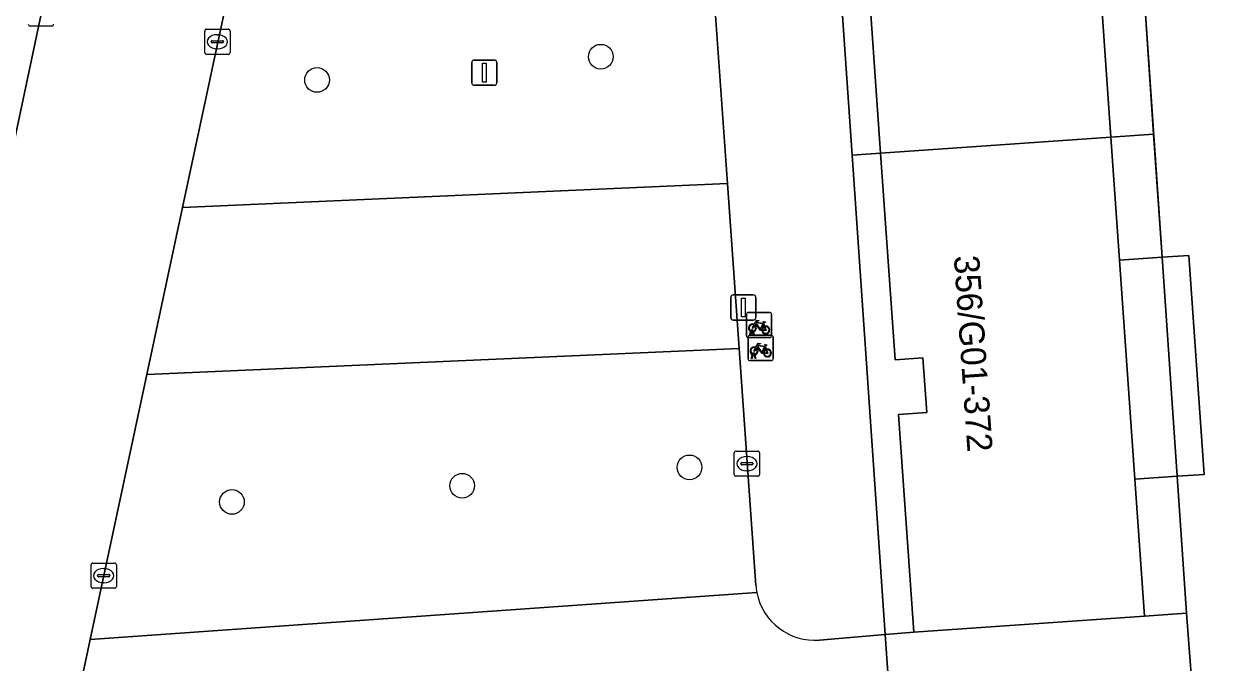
# Model space of a CAD drawing. Extents: x 161248 to 161848, y 384871 to 385383.
# Drawn here: x 161705.19 to 161753.01, y 385039.74 to 385065.04 of the extents above; entities that cross this region are included whole.
import ezdxf

# ---------------------------------------------------------------- set-up
doc = ezdxf.new("R2010")
doc.units = 0
for name, color, linetype in [('IMGEO_Boom', 7, 'Continuous'), ('IMGEO_Fietsenrek', 7, 'Continuous'), ('IMGEO_Kolk', 7, 'Continuous'), ('IMGEO_Lichtmast', 7, 'Continuous'), ('IMGEO_Pand', 7, 'Continuous'), ('IMGEO_Pand_nummerreeks', 7, 'Continuous'), ('IMGEO_Pand_overbouw', 7, 'Continuous'), ('IMGEO_Parkeervlak_open', 7, 'Continuous'), ('IMGEO_Rijbaan_lokaal_open', 7, 'Continuous'), ('IMGEO_Voetpad_open', 7, 'Continuous')]:
    doc.layers.add(name, color=color, linetype=linetype)

msp = doc.modelspace()

# ---------------------------------------------------------------- linework, layer by layer
at = {"layer": 'IMGEO_Boom'}
for centre in [(161728.021, 385063.749), (161716.786, 385062.828), (161731.533, 385047.481), (161722.532, 385046.752), (161713.416, 385046.112)]:
    msp.add_circle(centre, 0.489, dxfattribs=at)
at = {"layer": 'IMGEO_Fietsenrek'}
for p, q in [((161733.86, 385053.62), (161734.701, 385053.62)), ((161734.701, 385053.62), (161733.86, 385053.62)), ((161733.785, 385052.695), (161733.785, 385053.536)), ((161733.785, 385053.536), (161733.785, 385052.695)), ((161734.472, 385053.169), (161734.508, 385053.074)), ((161734.785, 385053.545), (161734.785, 385052.704)), ((161734.785, 385052.704), (161734.785, 385053.545)), ((161733.912, 385052.704), (161733.951, 385052.864)), ((161733.946, 385052.704), (161733.912, 385052.704)), ((161733.924, 385052.712), (161734.765, 385052.712)), ((161734.765, 385052.712), (161733.924, 385052.712)), ((161733.981, 385052.852), (161733.946, 385052.704)), ((161734.023, 385052.876), (161734.022, 385052.88)), ((161734.064, 385052.704), (161734.03, 385052.846)), ((161734.054, 385052.887), (161734.055, 385052.88)), ((161734.062, 385052.85), (161734.097, 385052.704)), ((161734.097, 385052.704), (161734.064, 385052.704)), ((161733.849, 385051.787), (161733.849, 385052.628)), ((161733.849, 385052.628), (161733.849, 385051.787)), ((161734.71, 385052.62), (161733.869, 385052.62)), ((161733.869, 385052.62), (161734.71, 385052.62)), ((161734.536, 385052.261), (161734.572, 385052.166)), ((161734.849, 385052.637), (161734.849, 385051.796)), ((161734.849, 385051.796), (161734.849, 385052.637)), ((161734.774, 385051.712), (161733.933, 385051.712)), ((161733.933, 385051.712), (161734.774, 385051.712)), ((161733.976, 385051.796), (161734.015, 385051.956)), ((161734.01, 385051.796), (161733.976, 385051.796)), ((161734.045, 385051.944), (161734.01, 385051.796)), ((161734.087, 385051.968), (161734.086, 385051.972)), ((161734.128, 385051.796), (161734.094, 385051.938)), ((161734.118, 385051.979), (161734.119, 385051.972)), ((161734.126, 385051.942), (161734.161, 385051.796)), ((161734.161, 385051.796), (161734.128, 385051.796))]:
    msp.add_line(p, q, dxfattribs=at)
for points in [[(161734.098, 385053.146), (161734.193, 385053.31), (161734.279, 385053.296), (161734.281, 385053.287), (161734.225, 385053.276), (161734.198, 385053.231), (161734.454, 385053.19)], [(161734.394, 385052.902), (161734.344, 385052.902), (161734.153, 385053.153), (161734.134, 385053.121)], [(161734.441, 385053.165), (161734.184, 385053.206), (161734.167, 385053.177), (161734.334, 385052.957), (161734.441, 385053.165)], [(161734.489, 385053.067), (161734.459, 385053.144), (161734.35, 385052.926), (161734.393, 385052.926)], [(161734.454, 385053.19), (161734.479, 385053.239), (161734.473, 385053.243), (161734.45, 385053.247), (161734.438, 385053.254), (161734.437, 385053.257), (161734.439, 385053.262), (161734.534, 385053.247), (161734.536, 385053.237), (161734.526, 385053.224), (161734.514, 385053.218), (161734.5, 385053.224), (161734.472, 385053.169)], [(161734.119, 385053.094), (161734.067, 385053.004), (161734.027, 385052.979), (161734.028, 385053.026), (161734.083, 385053.12)], [(161734.423, 385052.926), (161734.543, 385052.925), (161734.499, 385053.039)], [(161734.519, 385053.046), (161734.574, 385052.901), (161734.424, 385052.901)], [(161734.183, 385052.186), (161734.131, 385052.096), (161734.091, 385052.071), (161734.092, 385052.118), (161734.147, 385052.212)], [(161734.162, 385052.238), (161734.257, 385052.402), (161734.343, 385052.388), (161734.345, 385052.379), (161734.289, 385052.368), (161734.262, 385052.323), (161734.518, 385052.282)], [(161734.458, 385051.994), (161734.408, 385051.994), (161734.217, 385052.245), (161734.198, 385052.213)], [(161734.505, 385052.257), (161734.248, 385052.298), (161734.231, 385052.269), (161734.398, 385052.049), (161734.505, 385052.257)], [(161734.553, 385052.159), (161734.523, 385052.236), (161734.414, 385052.018), (161734.457, 385052.018)], [(161734.518, 385052.282), (161734.543, 385052.331), (161734.537, 385052.335), (161734.514, 385052.339), (161734.502, 385052.346), (161734.501, 385052.349), (161734.503, 385052.354), (161734.598, 385052.339), (161734.6, 385052.329), (161734.59, 385052.316), (161734.578, 385052.31), (161734.564, 385052.316), (161734.536, 385052.261)], [(161734.487, 385052.018), (161734.607, 385052.017), (161734.563, 385052.131)], [(161734.583, 385052.138), (161734.638, 385051.993), (161734.488, 385051.993)]]:
    msp.add_lwpolyline(points, dxfattribs=at)
for centre, radius, start, end in [((161733.863, 385053.542), 0.0779, 92.4484, 184.2845), ((161733.863, 385053.542), 0.0779, 92.4484, 184.2845), ((161734.707, 385053.542), 0.0779, 2.4484, 94.2845), ((161734.707, 385053.542), 0.0779, 2.4484, 94.2845), ((161734.025, 385053.005), 0.159, 62.6766, 242.1369), ((161734.025, 385053.005), 0.129, 63.3192, 238.903), ((161733.863, 385052.698), 0.0779, 182.4484, 274.2845), ((161733.863, 385052.698), 0.0779, 182.4484, 274.2845), ((161733.927, 385052.634), 0.0779, 92.4484, 184.2845), ((161733.927, 385052.634), 0.0779, 92.4484, 184.2845), ((161734.005, 385052.876), 0.0499, 12.8025, 158.6934), ((161734.025, 385053.005), 0.159, 253.9967, 271.7867), ((161734.005, 385052.876), 0.0174, 12.8025, 163.4502), ((161734.025, 385053.005), 0.129, 253.415, 269.0204), ((161734.025, 385053.005), 0.129, 283.6043, 43.4302), ((161734.025, 385053.005), 0.159, 283.5766, 46.6042), ((161734.552, 385052.921), 0.159, 113.3408, 178.3217), ((161734.552, 385052.921), 0.159, 187.0065, 105.7708), ((161734.552, 385052.921), 0.129, 113.923, 177.9556), ((161734.552, 385052.921), 0.129, 188.6715, 104.5883), ((161734.707, 385052.698), 0.0779, 272.4484, 4.2845), ((161734.707, 385052.698), 0.0779, 272.4484, 4.2845), ((161734.771, 385052.634), 0.0779, 2.4484, 94.2845), ((161734.771, 385052.634), 0.0779, 2.4484, 94.2845), ((161734.089, 385052.097), 0.159, 62.6766, 242.1369), ((161734.089, 385052.097), 0.129, 63.3192, 238.903), ((161734.089, 385052.097), 0.129, 283.6043, 43.4302), ((161734.089, 385052.097), 0.159, 283.5766, 46.6042), ((161734.616, 385052.013), 0.159, 187.0065, 105.7708), ((161733.927, 385051.79), 0.0779, 182.4484, 274.2845), ((161733.927, 385051.79), 0.0779, 182.4484, 274.2845), ((161734.069, 385051.968), 0.0499, 12.8025, 158.6934), ((161734.089, 385052.097), 0.159, 253.9967, 271.7867), ((161734.069, 385051.968), 0.0174, 12.8025, 163.4502), ((161734.089, 385052.097), 0.129, 253.415, 269.0204), ((161734.616, 385052.013), 0.159, 113.3408, 178.3217), ((161734.616, 385052.013), 0.129, 113.923, 177.9556), ((161734.616, 385052.013), 0.129, 188.6715, 104.5883), ((161734.771, 385051.79), 0.0779, 272.4484, 4.2845), ((161734.771, 385051.79), 0.0779, 272.4484, 4.2845)]:
    msp.add_arc(centre, radius, start, end, dxfattribs=at)
at = {"layer": 'IMGEO_Kolk'}
for p, q in [((161706.281, 385064.965), (161705.429, 385064.965)), ((161712.34, 385063.914), (161712.34, 385064.766)), ((161712.415, 385064.84), (161713.267, 385064.84)), ((161712.828, 385064.62), (161712.853, 385064.62)), ((161713.341, 385064.766), (161713.341, 385063.914)), ((161712.599, 385064.334), (161712.599, 385064.346)), ((161713.037, 385064.297), (161712.639, 385064.297)), ((161712.642, 385064.383), (161713.04, 385064.383)), ((161713.083, 385064.346), (161713.083, 385064.334)), ((161713.267, 385063.84), (161712.415, 385063.84)), ((161712.851, 385064.06), (161712.826, 385064.06)), ((161733.305, 385047.201), (161733.305, 385048.053)), ((161733.38, 385048.127), (161734.232, 385048.127)), ((161733.793, 385047.907), (161733.818, 385047.907)), ((161734.306, 385048.053), (161734.306, 385047.201)), ((161733.564, 385047.621), (161733.564, 385047.633)), ((161734.002, 385047.584), (161733.604, 385047.584)), ((161733.607, 385047.67), (161734.005, 385047.67)), ((161734.048, 385047.633), (161734.048, 385047.621)), ((161734.232, 385047.127), (161733.38, 385047.127)), ((161733.816, 385047.347), (161733.791, 385047.347)), ((161707.84, 385042.764), (161707.84, 385043.616)), ((161707.915, 385043.69), (161708.767, 385043.69)), ((161708.841, 385043.616), (161708.841, 385042.764)), ((161708.099, 385043.184), (161708.099, 385043.196)), ((161708.537, 385043.147), (161708.139, 385043.147)), ((161708.142, 385043.233), (161708.54, 385043.233)), ((161708.328, 385043.47), (161708.353, 385043.47)), ((161708.583, 385043.196), (161708.583, 385043.184)), ((161708.767, 385042.69), (161707.915, 385042.69)), ((161708.351, 385042.91), (161708.326, 385042.91))]:
    msp.add_line(p, q, dxfattribs=at)
for points in [[(161706.281, 385064.965), (161705.429, 385064.965)], [(161712.34, 385063.914), (161712.34, 385064.766)], [(161712.415, 385064.84), (161713.267, 385064.84)], [(161713.341, 385064.766), (161713.341, 385063.914)], [(161713.267, 385063.84), (161712.415, 385063.84)], [(161733.305, 385047.201), (161733.305, 385048.053)], [(161733.38, 385048.127), (161734.232, 385048.127)], [(161734.306, 385048.053), (161734.306, 385047.201)], [(161734.232, 385047.127), (161733.38, 385047.127)], [(161707.84, 385042.764), (161707.84, 385043.616)], [(161707.915, 385043.69), (161708.767, 385043.69)], [(161708.841, 385043.616), (161708.841, 385042.764)], [(161708.767, 385042.69), (161707.915, 385042.69)]]:
    msp.add_lwpolyline(points, dxfattribs=at)
for centre, radius, start, end in [((161705.431, 385065.041), 0.0765, 181.552, 268.448), ((161705.431, 385065.041), 0.0765, 181.552, 268.448), ((161706.279, 385065.041), 0.0765, 271.552, 358.448), ((161706.279, 385065.041), 0.0765, 271.552, 358.448), ((161712.417, 385064.764), 0.0765, 91.552, 178.448), ((161712.417, 385064.764), 0.0765, 91.552, 178.448), ((161713.265, 385064.764), 0.0765, 1.552, 88.448), ((161713.265, 385064.764), 0.0765, 1.552, 88.448), ((161712.639, 385064.343), 0.0403, 85.8775, 175.7526), ((161712.636, 385064.333), 0.0366, 178.938, 274.7102), ((161713.04, 385064.34), 0.043, 264.8664, 352.4533), ((161713.044, 385064.345), 0.0386, 1.7309, 96.639), ((161712.417, 385063.916), 0.0765, 181.552, 268.448), ((161712.417, 385063.916), 0.0765, 181.552, 268.448), ((161713.265, 385063.916), 0.0765, 271.552, 358.448), ((161713.265, 385063.916), 0.0765, 271.552, 358.448), ((161733.382, 385048.051), 0.0765, 91.552, 178.448), ((161733.382, 385048.051), 0.0765, 91.552, 178.448), ((161734.23, 385048.051), 0.0765, 1.552, 88.448), ((161734.23, 385048.051), 0.0765, 1.552, 88.448), ((161733.604, 385047.63), 0.0403, 85.8775, 175.7526), ((161733.601, 385047.62), 0.0366, 178.938, 274.7102), ((161734.005, 385047.627), 0.043, 264.8664, 352.4533), ((161734.009, 385047.632), 0.0386, 1.7309, 96.639), ((161733.382, 385047.203), 0.0765, 181.552, 268.448), ((161733.382, 385047.203), 0.0765, 181.552, 268.448), ((161734.23, 385047.203), 0.0765, 271.552, 358.448), ((161734.23, 385047.203), 0.0765, 271.552, 358.448), ((161707.917, 385043.614), 0.0765, 91.552, 178.448), ((161707.917, 385043.614), 0.0765, 91.552, 178.448), ((161708.765, 385043.614), 0.0765, 1.552, 88.448), ((161708.765, 385043.614), 0.0765, 1.552, 88.448), ((161708.139, 385043.193), 0.0403, 85.8775, 175.7526), ((161708.136, 385043.183), 0.0366, 178.938, 274.7102), ((161708.54, 385043.19), 0.043, 264.8664, 352.4533), ((161708.544, 385043.195), 0.0386, 1.7309, 96.639), ((161707.917, 385042.766), 0.0765, 181.552, 268.448), ((161707.917, 385042.766), 0.0765, 181.552, 268.448), ((161708.765, 385042.766), 0.0765, 271.552, 358.448), ((161708.765, 385042.766), 0.0765, 271.552, 358.448)]:
    msp.add_arc(centre, radius, start, end, dxfattribs=at)
for centre, major_axis, ratio, start_param, end_param in [((161712.827, 385064.34), (-0.387, 0.002), 0.722429, 4.712389, 7.853982), ((161712.852, 385064.34), (-0.39, 0.002), 0.717154, 1.570796, 4.712389), ((161733.792, 385047.627), (-0.387, 0.002), 0.722429, 4.712389, 7.853982), ((161733.817, 385047.627), (-0.39, 0.002), 0.717154, 1.570796, 4.712389), ((161708.327, 385043.19), (-0.387, 0.002), 0.722429, 4.712389, 7.853982), ((161708.352, 385043.19), (-0.39, 0.002), 0.717154, 1.570796, 4.712389)]:
    msp.add_ellipse(centre, major_axis=major_axis, ratio=ratio, start_param=start_param, end_param=end_param, dxfattribs=at)
at = {"layer": 'IMGEO_Lichtmast'}
for p, q in [((161722.913, 385062.717), (161722.913, 385063.517)), ((161722.913, 385063.517), (161722.913, 385062.717)), ((161723.013, 385063.617), (161723.803, 385063.617)), ((161723.803, 385063.617), (161723.013, 385063.617)), ((161723.903, 385063.517), (161723.903, 385062.717)), ((161723.903, 385062.717), (161723.903, 385063.517)), ((161723.803, 385062.617), (161723.013, 385062.617)), ((161723.013, 385062.617), (161723.803, 385062.617)), ((161733.167, 385053.414), (161733.167, 385054.214)), ((161733.167, 385054.214), (161733.167, 385053.414)), ((161733.267, 385054.314), (161734.057, 385054.314)), ((161734.057, 385054.314), (161733.267, 385054.314)), ((161734.157, 385054.214), (161734.157, 385053.414)), ((161734.157, 385053.414), (161734.157, 385054.214)), ((161734.057, 385053.314), (161733.267, 385053.314)), ((161733.267, 385053.314), (161734.057, 385053.314))]:
    msp.add_line(p, q, dxfattribs=at)
for points in [[(161723.333, 385063.492), (161723.483, 385063.492), (161723.483, 385062.742), (161723.333, 385062.742), (161723.333, 385063.492)], [(161733.587, 385054.189), (161733.737, 385054.189), (161733.737, 385053.439), (161733.587, 385053.439), (161733.587, 385054.189)]]:
    msp.add_lwpolyline(points, dxfattribs=at)
for centre, start, end in [((161723.013, 385063.517), 90, 180), ((161723.013, 385063.517), 90, 180), ((161723.803, 385063.517), 0, 90), ((161723.803, 385063.517), 360, 90), ((161723.013, 385062.717), 180, 270), ((161723.013, 385062.717), 180, 270), ((161723.803, 385062.717), 270, 0), ((161723.803, 385062.717), 270, 0), ((161733.267, 385054.214), 90, 180), ((161733.267, 385054.214), 90, 180), ((161734.057, 385054.214), 0, 90), ((161734.057, 385054.214), 360, 90), ((161733.267, 385053.414), 180, 270), ((161733.267, 385053.414), 180, 270), ((161734.057, 385053.414), 270, 0), ((161734.057, 385053.414), 270, 0)]:
    msp.add_arc(centre, 0.1, start, end, dxfattribs=at)
at = {"layer": 'IMGEO_Pand'}
for points in [[(161746.929, 385079.053), (161737.87, 385078.421), (161738.443, 385070.205), (161739.46, 385070.276), (161739.606, 385068.174), (161738.531, 385068.099), (161739.101, 385059.923), (161748.22, 385060.558), (161747.874, 385065.514), (161747.267, 385074.213)], [(161748.22, 385060.558), (161739.101, 385059.923), (161739.671, 385051.745), (161740.776, 385051.823), (161740.928, 385049.648), (161739.813, 385049.57), (161740.414, 385040.955), (161749.543, 385041.591), (161749.165, 385047.009), (161748.559, 385055.688)]]:
    msp.add_lwpolyline(points, close=True, dxfattribs=at)
at = {"layer": 'IMGEO_Pand_overbouw'}
for points in [[(161748.97, 385074.332), (161748.637, 385079.171), (161746.929, 385079.053), (161747.267, 385074.213), (161747.874, 385065.514), (161748.22, 385060.558), (161749.908, 385060.676), (161749.568, 385065.633)], [(161739.46, 385070.276), (161738.443, 385070.205), (161737.87, 385078.421), (161736.69, 385078.339), (161737.968, 385059.844), (161739.101, 385059.923), (161738.531, 385068.099), (161739.606, 385068.174)], [(161750.243, 385055.806), (161749.908, 385060.676), (161748.22, 385060.558), (161748.559, 385055.688), (161749.165, 385047.009), (161749.543, 385041.591), (161751.212, 385041.71), (161750.84, 385047.126)], [(161740.776, 385051.823), (161739.671, 385051.745), (161739.101, 385059.923), (161737.968, 385059.844), (161739.279, 385040.858), (161740.414, 385040.955), (161739.813, 385049.57), (161740.928, 385049.648)], [(161752.563, 385037.102), (161751.565, 385037.026), (161751.525, 385037.552), (161751.212, 385041.71), (161749.543, 385041.591), (161740.414, 385040.955), (161739.279, 385040.858), (161739.564, 385036.724), (161739.938, 385031.316), (161740.196, 385031.334), (161740.116, 385032.512), (161748.302, 385033.074), (161748.382, 385031.895), (161751.933, 385032.139), (161751.957, 385031.79), (161752.955, 385031.859), (161752.929, 385032.208)]]:
    msp.add_lwpolyline(points, close=True, dxfattribs=at)
at = {"layer": 'IMGEO_Parkeervlak_open'}
msp.add_lwpolyline([(161732.316, 385068.912), (161713.621, 385067.908), (161711.46, 385057.779), (161733.036, 385058.72)], close=True, dxfattribs=at)
for points in [[(161733.497, 385052.19), (161710.048, 385051.158), (161707.807, 385040.656), (161734.198, 385042.52)], [(161734.161, 385042.799), (161733.497, 385052.19)]]:
    msp.add_lwpolyline(points, dxfattribs=at)
msp.add_arc((161736.954, 385043.027), 2.802, 184.676, 190.4326, dxfattribs=at)
at = {"layer": 'IMGEO_Rijbaan_lokaal_open'}
for points in [[(161700.158, 385004.616), (161701.87, 385012.717), (161702.148, 385014.035), (161704.227, 385023.875), (161705.595, 385030.288), (161707.807, 385040.656), (161710.048, 385051.158), (161711.46, 385057.779), (161713.621, 385067.908), (161718.737, 385091.888), (161723.047, 385104.286)], [(161747.268, 385099.1), (161747.339, 385098.062), (161747.696, 385092.869), (161748.718, 385092.94), (161749.325, 385084.251), (161748.293, 385084.179), (161748.97, 385074.332), (161750.01, 385074.405), (161750.618, 385065.706), (161749.568, 385065.633), (161750.243, 385055.806), (161751.304, 385055.88), (161751.91, 385047.201), (161750.84, 385047.126), (161751.212, 385041.71), (161751.525, 385037.552), (161752.677, 385037.632), (161753.631, 385037.858)], [(161697.639, 385095.416), (161705.809, 385093.105), (161706.222, 385092.971), (161706.735, 385092.759), (161707.226, 385092.501), (161707.693, 385092.201), (161708.131, 385091.86), (161708.537, 385091.482), (161708.907, 385091.068), (161709.239, 385090.623), (161709.53, 385090.151), (161709.777, 385089.654), (161709.98, 385089.137), (161710.135, 385088.604), (161710.242, 385088.06), (161710.299, 385087.508), (161710.308, 385086.953), (161710.267, 385086.4), (161710.176, 385085.852), (161709.086, 385080.709), (161707.731, 385074.281), (161707.198, 385071.757), (161706.154, 385066.816), (161704.242, 385057.766)], [(161734.198, 385042.52), (161707.807, 385040.656), (161705.595, 385030.288)], [(161711.062, 385034.751), (161739.564, 385036.724), (161739.279, 385040.858)], [(161739.279, 385040.858), (161736.683, 385040.636)]]:
    msp.add_lwpolyline(points, dxfattribs=at)
for points in [[(161733.036, 385058.72), (161711.46, 385057.779), (161710.048, 385051.158), (161733.497, 385052.19)], [(161750.84, 385047.126), (161751.91, 385047.201), (161751.304, 385055.88), (161750.243, 385055.806)], [(161751.212, 385041.71), (161749.543, 385041.591), (161740.414, 385040.955), (161739.279, 385040.858), (161739.564, 385036.724), (161751.525, 385037.552)]]:
    msp.add_lwpolyline(points, close=True, dxfattribs=at)
msp.add_arc((161736.497, 385042.972), 2.343, 191.1184, 274.5465, dxfattribs=at)
at = {"layer": 'IMGEO_Voetpad_open'}
for points in [[(161737.968, 385059.844), (161736.69, 385078.339), (161735.386, 385097.218), (161736.522, 385097.301), (161745.612, 385097.935), (161747.339, 385098.062), (161747.268, 385099.1)], [(161730.273, 385097.834), (161730.444, 385095.419), (161730.886, 385089.156), (161731.214, 385084.509), (161731.901, 385074.781), (161732.316, 385068.912), (161733.036, 385058.72), (161733.497, 385052.19), (161734.161, 385042.799)], [(161704.242, 385057.766), (161706.154, 385066.816)], [(161736.683, 385040.636), (161739.279, 385040.858), (161737.968, 385059.844)]]:
    msp.add_lwpolyline(points, dxfattribs=at)
for points in [[(161737.968, 385059.844), (161739.101, 385059.923), (161738.531, 385068.099), (161739.606, 385068.174), (161739.46, 385070.276), (161738.443, 385070.205), (161737.87, 385078.421), (161736.69, 385078.339)], [(161749.568, 385065.633), (161747.874, 385065.514), (161748.22, 385060.558), (161748.559, 385055.688), (161750.243, 385055.806)], [(161740.776, 385051.823), (161739.671, 385051.745), (161739.101, 385059.923), (161737.968, 385059.844), (161739.279, 385040.858), (161740.414, 385040.955), (161739.813, 385049.57), (161740.928, 385049.648)], [(161750.243, 385055.806), (161748.559, 385055.688), (161749.165, 385047.009), (161750.84, 385047.126)], [(161750.84, 385047.126), (161749.165, 385047.009), (161749.543, 385041.591), (161751.212, 385041.71)]]:
    msp.add_lwpolyline(points, close=True, dxfattribs=at)
for centre, radius, start, end in [((161736.954, 385043.027), 2.802, 184.676, 190.4326), ((161736.497, 385042.972), 2.343, 191.1184, 274.5465)]:
    msp.add_arc(centre, radius, start, end, dxfattribs=at)

# ---------------------------------------------------------------- texts
at = {"layer": 'IMGEO_Pand_nummerreeks'}
msp.add_text('356/G01-372', height=1, rotation=273.9976, dxfattribs=at).set_placement((161741.998, 385055.85))

doc.saveas('drawing.dxf')
